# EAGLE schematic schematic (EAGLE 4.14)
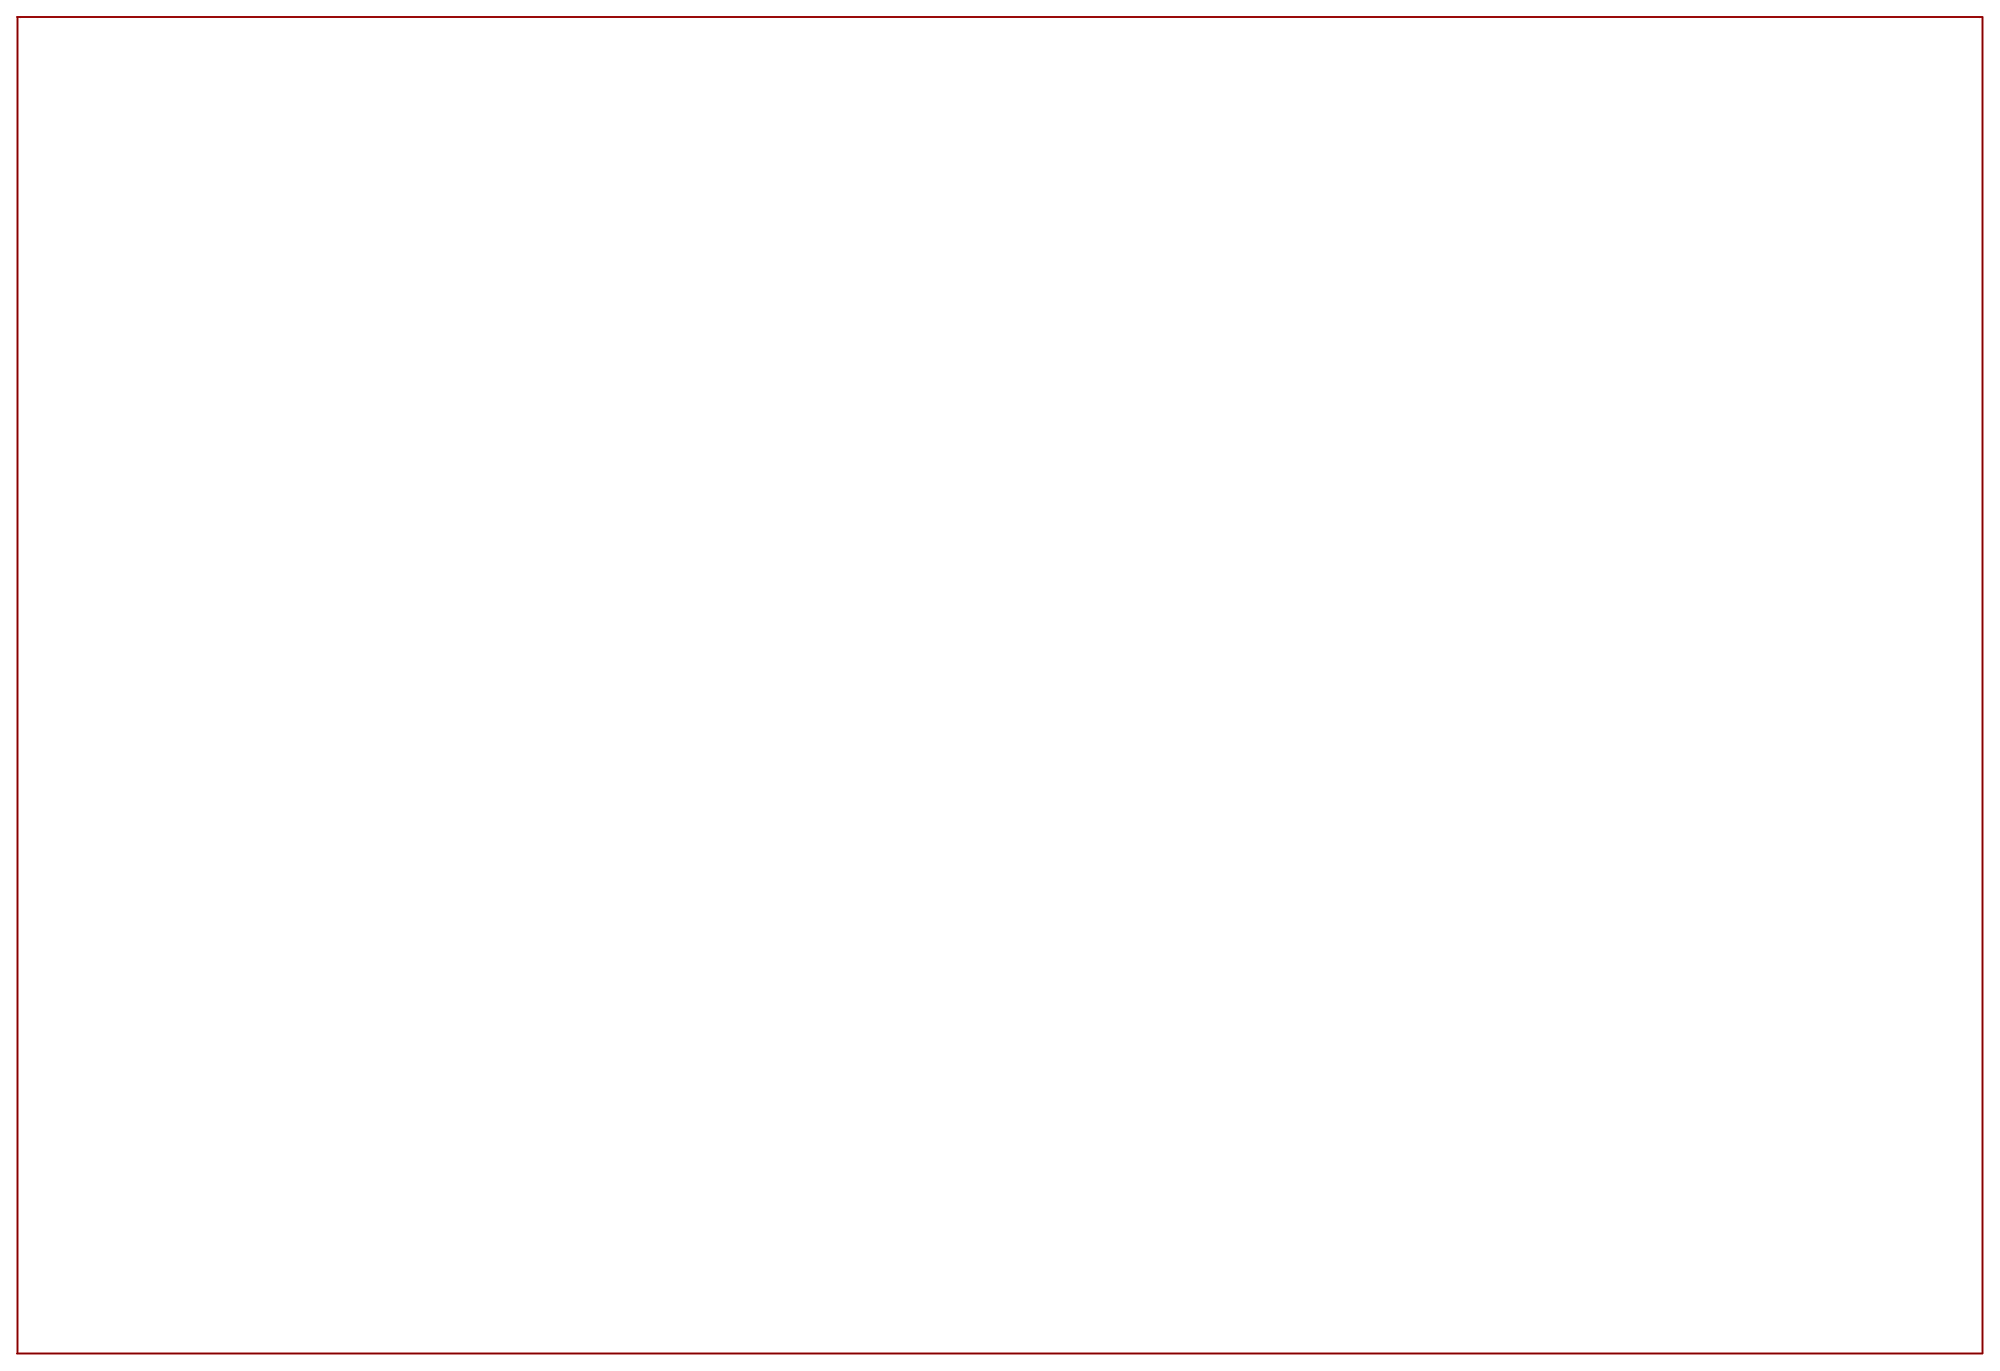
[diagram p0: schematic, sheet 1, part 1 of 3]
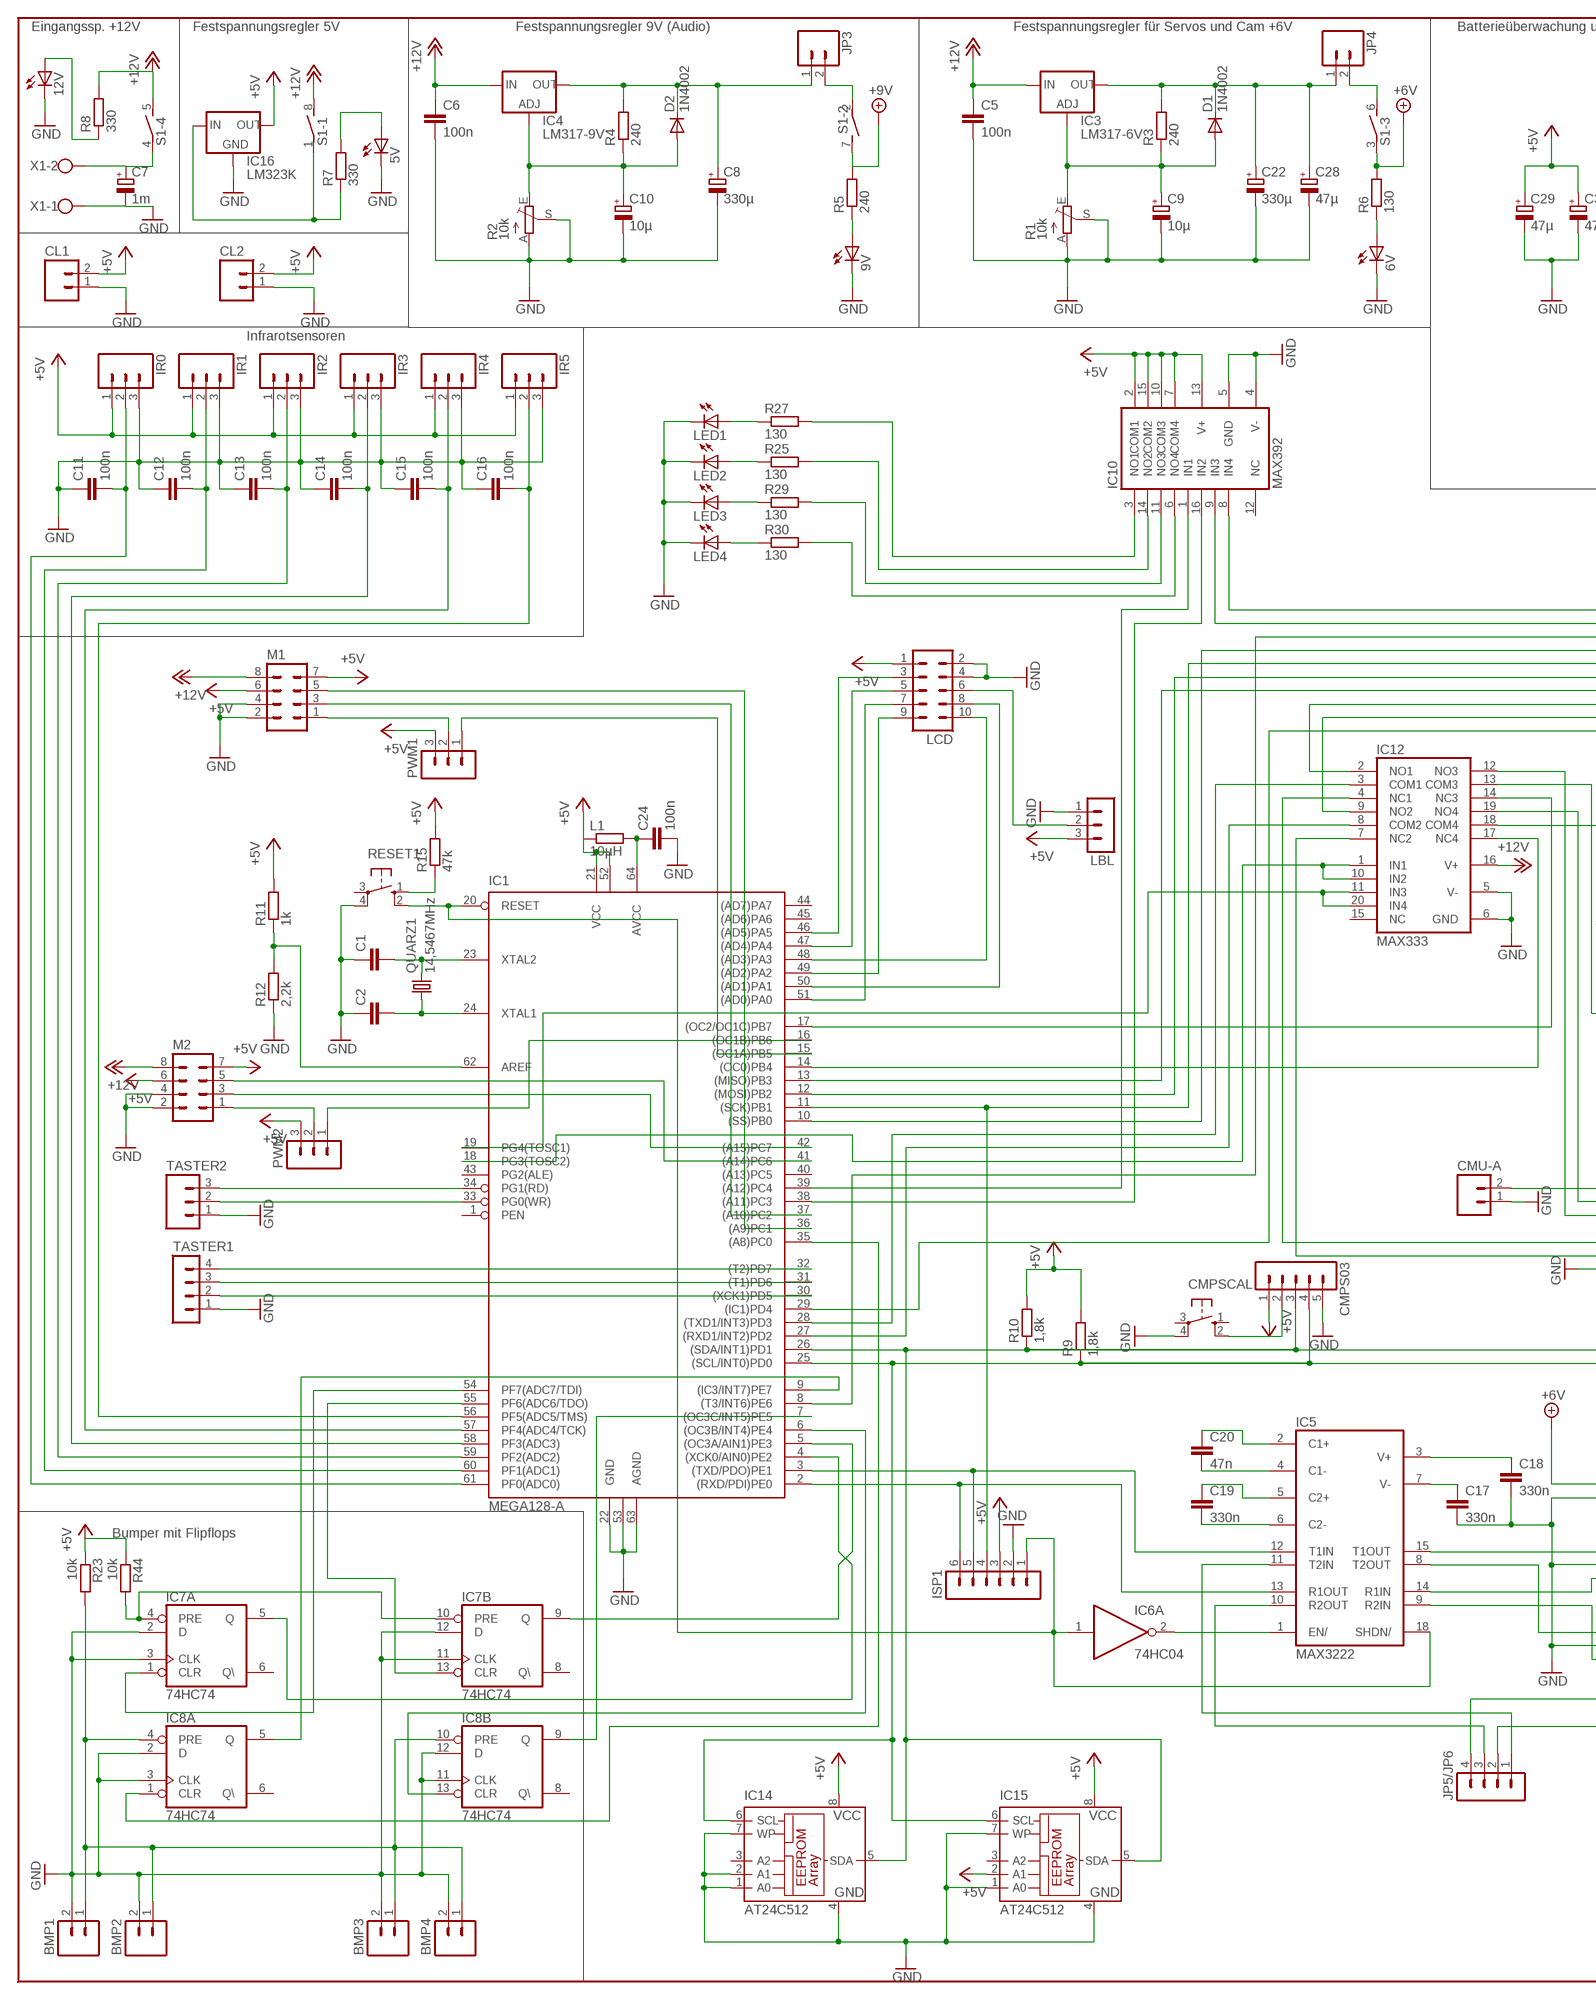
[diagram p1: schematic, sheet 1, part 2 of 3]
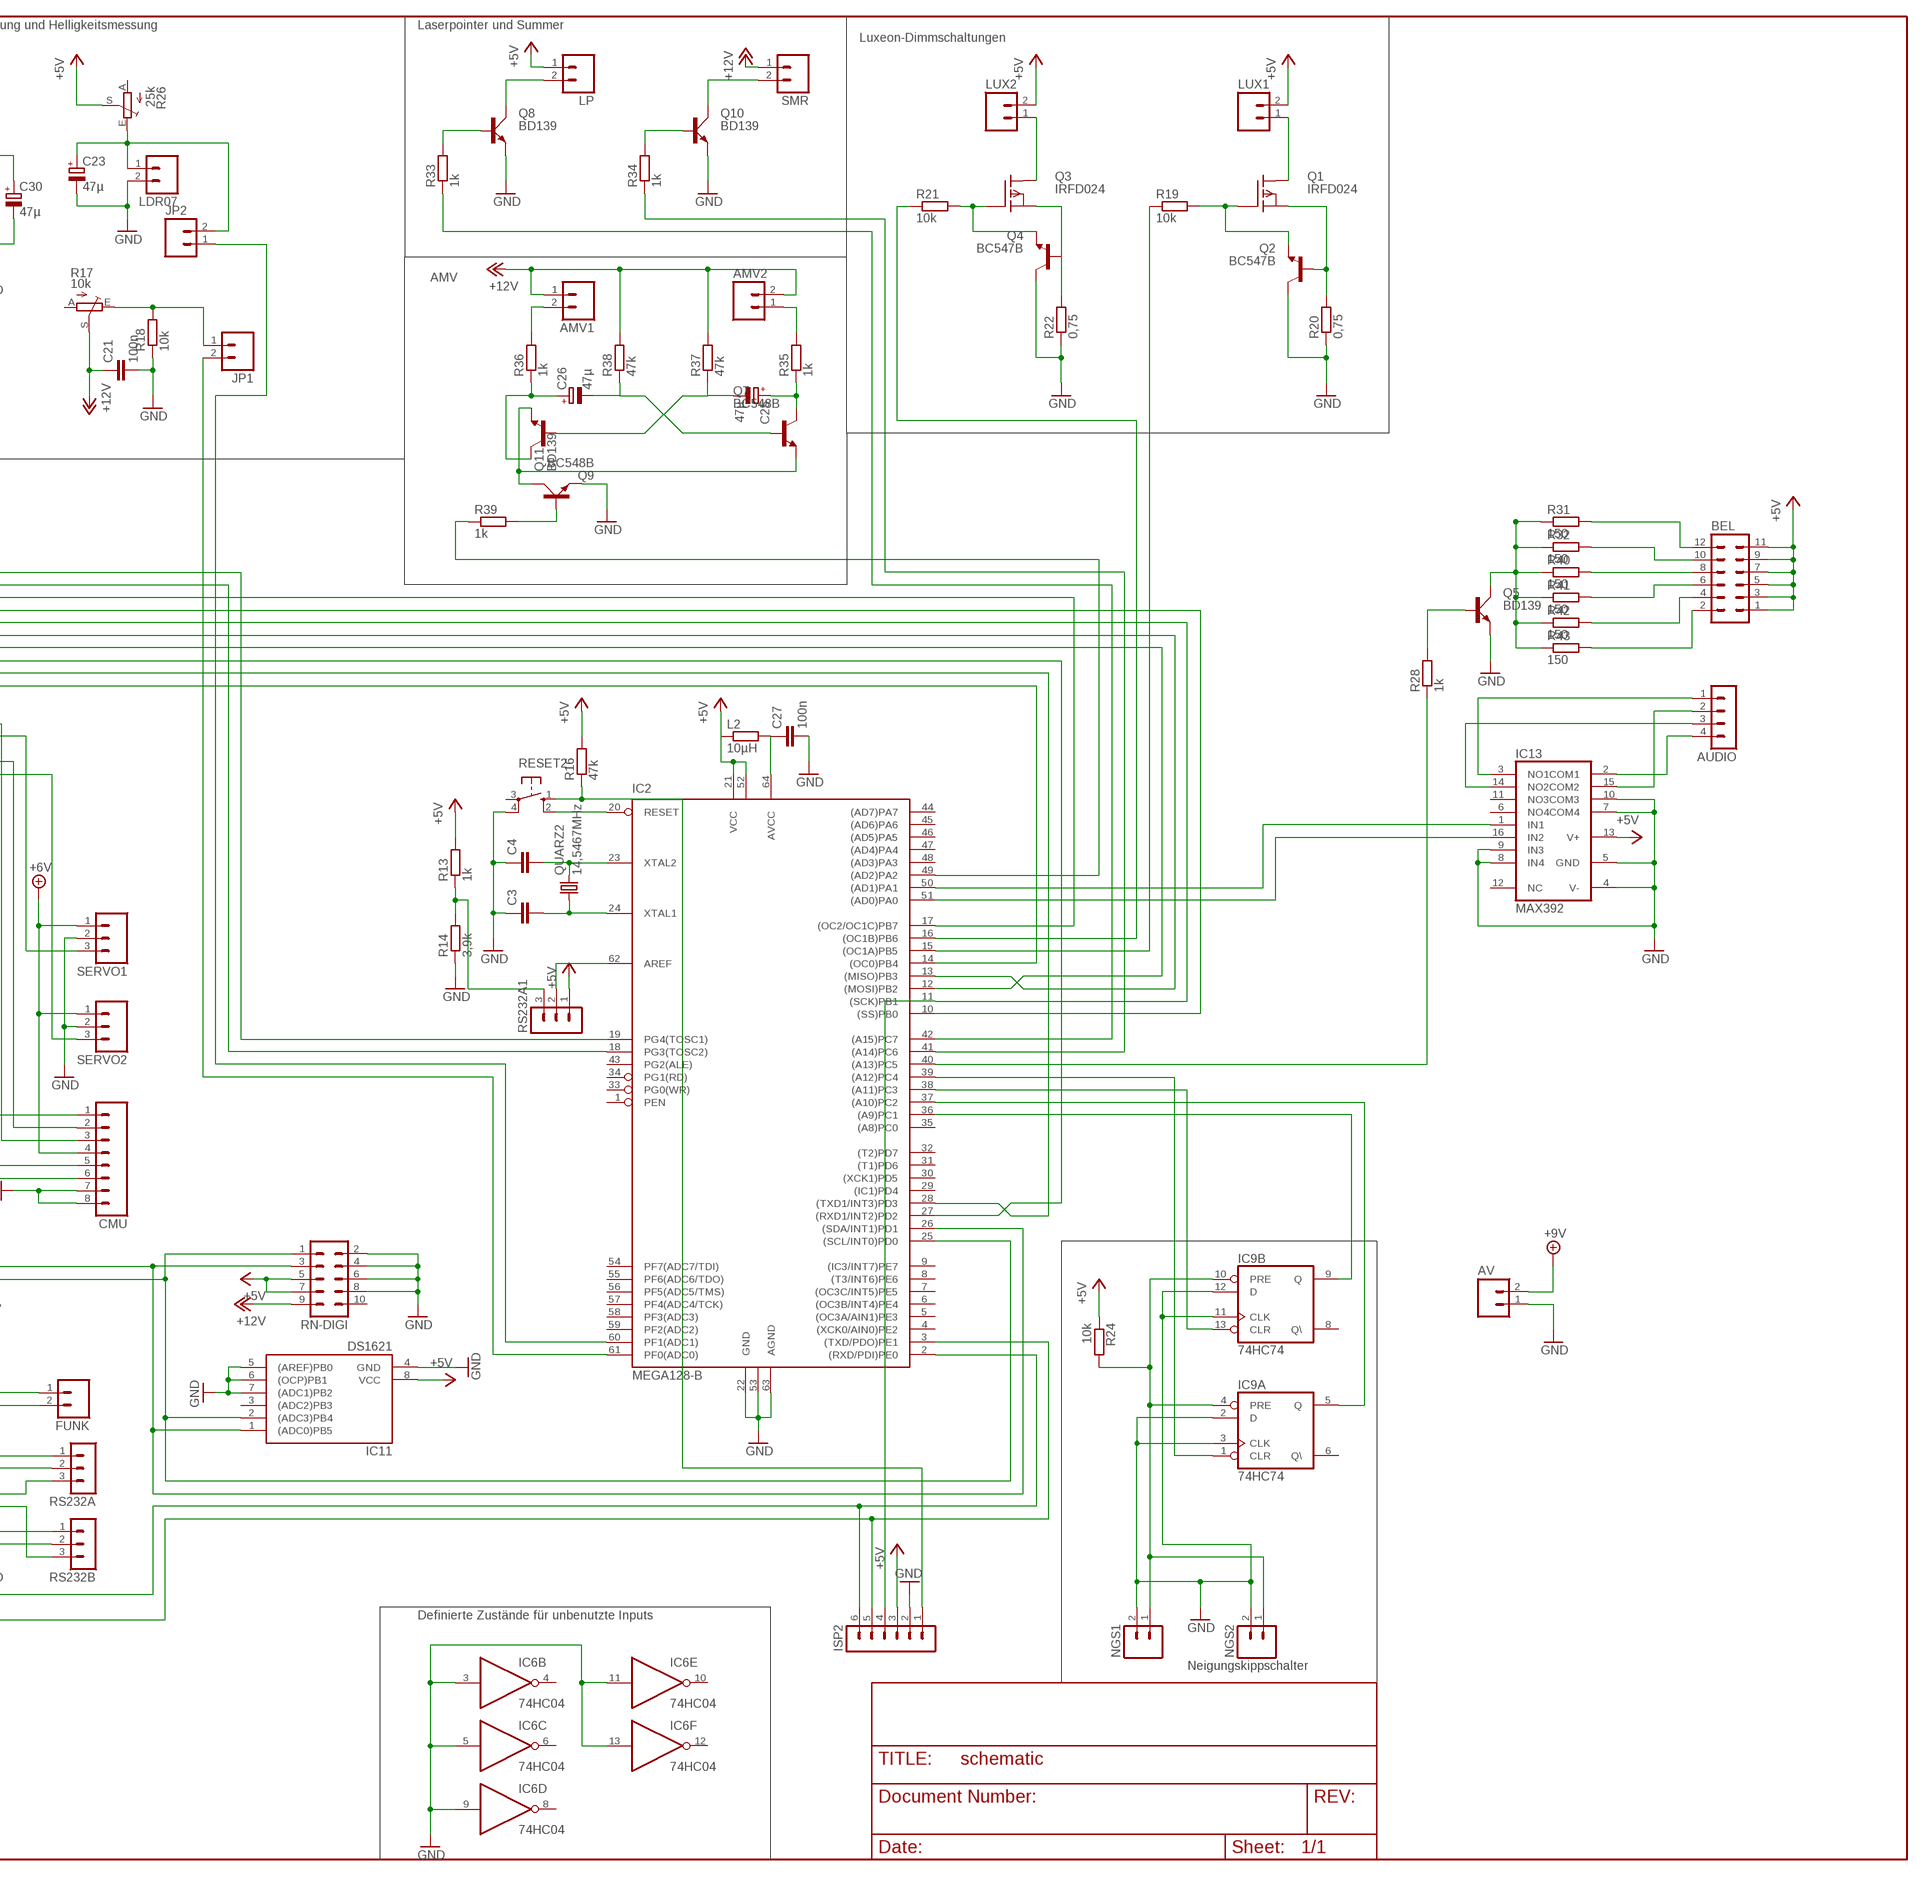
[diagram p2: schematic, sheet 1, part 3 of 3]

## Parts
5V  LEDCHIPLED_1206  [CHIPLED_1206]
6V  LEDCHIPLED_1206  [CHIPLED_1206]
9V  LEDCHIPLED_1206  [CHIPLED_1206]
12V  LEDCHIPLED_1206  [CHIPLED_1206]
AMV1  M02  [02P]
AMV2  M02  [02P]
AUDIO  MA04-1  [MA04-1]
AV  M02  [02P]
BEL  MA06-2  [MA06-2]
BMP1  M02  [02P]
BMP2  M02  [02P]
BMP3  M02  [02P]
BMP4  M02  [02P]
C1  C-EUC0805  [C0805]
C2  C-EUC0805  [C0805]
C3  C-EUC0805  [C0805]
C4  C-EUC0805  [C0805]
C5  100n  C-EUC1206  [C1206]
C6  100n  C-EUC1206  [C1206]
C7  1m  CPOL-EUE5-10.5  [E5-10,5]
C8  330µ  CPOL-EUE3.5-8  [E3,5-8]
C9  10µ  CPOL-EUE2-5  [E2-5]
C10  10µ  CPOL-EUE2-5  [E2-5]
C11  100n  C-EUC1206  [C1206]
C12  100n  C-EUC1206  [C1206]
C13  100n  C-EUC1206  [C1206]
C14  100n  C-EUC1206  [C1206]
C15  100n  C-EUC1206  [C1206]
C16  100n  C-EUC1206  [C1206]
C17  330n  C-EUC1812  [C1812]
C18  330n  C-EUC1812  [C1812]
C19  330n  C-EUC1812  [C1812]
C20  47n  C-EUC1206  [C1206]
C21  100n  C-EUC1206  [C1206]
C22  330µ  CPOL-EUE3.5-8  [E3,5-8]
C23  47µ  CPOL-EUE2-5  [E2-5]
C24  100n  C-EUC1206  [C1206]
C25  47µ  CPOL-EUE2-5  [E2-5]
C26  47µ  CPOL-EUE2-5  [E2-5]
C27  100n  C-EUC1206  [C1206]
C28  47µ  CPOL-EUE2-5  [E2-5]
C29  47µ  CPOL-EUE2-5  [E2-5]
C30  47µ  CPOL-EUE2-5  [E2-5]
CL1  M02  [02P]
CL2  M02  [02P]
CMPS03  MA05-1  [MA05-1]
CMPSCAL  10-XX  [B3F-10XX]
CMU  M08  [08P]
CMU-A  M02  [02P]
D1  1N4002  1N4004  [DO41-10]
D2  1N4002  1N4004  [DO41-10]
FUNK  M02  [02P]
IC1  MEGA128-A  [TQFP64-AEB]
IC2  MEGA128-B  MEGA128-A  [TQFP64-AEB]
IC3  LM317-6V  LM317TL  [317TL]
IC4  LM317-9V  LM317TL  [317TL]
IC5  MAX3222  MAX3222CPN  [DIL18]
IC6  74HC04  74HCT04D  [SO14]
IC7  74HC74  74HC74N  [DIL14]
IC8  74HC74  74HC74N  [DIL14]
IC9  74HC74  74HC74N  [DIL14]
IC10  MAX392  MAX392CSE  [SO16]
IC11  DS1621  TINY15LP  [DIL08]
IC12  MAX333  MAX333ACPP  [DIL20]
IC13  MAX392  MAX392CSE  [SO16]
IC14  AT24C512  24C01CP  [DIL8]
IC15  AT24C512  24C01CP  [DIL8]
IC16  LM323K  LM323-TO3  [TO3-K02]
IR0  M03  [03P]
IR1  M03  [03P]
IR2  M03  [03P]
IR3  M03  [03P]
IR4  M03  [03P]
IR5  M03  [03P]
ISP1  MA06-1  [MA06-1]
ISP2  MA06-1  [MA06-1]
JP1  M02  [02P]
JP2  M02  [02P]
JP3  M02  [02P]
JP4  M02  [02P]
JP5/JP6  MA04-1  [MA04-1]
L1  10µH  R-EU_R1206  [R1206]
L2  10µH  R-EU_R1206  [R1206]
LBL  MA03-1  [MA03-1]
LCD  ML10  [ML10]
LDR07  M02  [02P]
LED1  LEDCHIPLED_1206  [CHIPLED_1206]
LED2  LEDCHIPLED_1206  [CHIPLED_1206]
LED3  LEDCHIPLED_1206  [CHIPLED_1206]
LED4  LEDCHIPLED_1206  [CHIPLED_1206]
LP  M02  [02P]
LUX1  M02  [02P]
LUX2  M02  [02P]
M1  MA04-2  [MA04-2]
M2  MA04-2  [MA04-2]
NGS1  M02  [02P]
NGS2  M02  [02P]
PWM1  MA03-1  [MA03-1]
PWM2  MA03-1  [MA03-1]
Q1  IRFD024  IRFD9210  [DIL04]
Q2  BC547B  [TO92]
Q3  IRFD024  IRFD9210  [DIL04]
Q4  BC547B  [TO92]
Q5  BD139  [TO126AV]
Q7  BC548B  [TO92-EBC]
Q8  BD139  [TO126AV]
Q9  BC548B  [TO92-EBC]
Q10  BD139  [TO126AV]
Q11  BD139  [TO126AV]
QUARZ1  14,5467MHz  CRYTALHC49UP  [HC49UP]
QUARZ2  14,5467MHz  CRYTALHC49UP  [HC49UP]
R1  10k  TRIM_EU-ST10  [ST10]
R2  10k  TRIM_EU-ST10  [ST10]
R3  240  R-EU_R1206  [R1206]
R4  240  R-EU_R1206  [R1206]
R5  240  R-EU_R0805  [R0805]
R6  130  R-EU_R0805  [R0805]
R7  330  R-EU_R0805  [R0805]
R8  330  R-EU_R0805  [R0805]
R9  1,8k  R-EU_R0805  [R0805]
R10  1,8k  R-EU_R0805  [R0805]
R11  1k  R-EU_R0805  [R0805]
R12  2,2k  R-EU_R0805  [R0805]
R13  1k  R-EU_R0805  [R0805]
R14  3,9k  R-EU_R0805  [R0805]
R15  47k  R-EU_R0805  [R0805]
R16  47k  R-EU_R0805  [R0805]
R17  10k  TRIM_EU-S43P  [SP19L]
R18  10k  R-EU_R0805  [R0805]
R19  10k  R-EU_R0805  [R0805]
R20  0,75  R-EU_0411/15  [0411/15]
R21  10k  R-EU_R0805  [R0805]
R22  0,75  R-EU_0411/15  [0411/15]
R23  10k  R-EU_R0805  [R0805]
R24  10k  R-EU_R0805  [R0805]
R25  130  R-EU_R0805  [R0805]
R26  25k  TRIM_EU-ST10  [ST10]
R27  130  R-EU_R0805  [R0805]
R28  1k  R-EU_R0805  [R0805]
R29  130  R-EU_R0805  [R0805]
R30  130  R-EU_R0805  [R0805]
R31  150  R-EU_R0805  [R0805]
R32  150  R-EU_R0805  [R0805]
R33  1k  R-EU_R0805  [R0805]
R34  1k  R-EU_R0805  [R0805]
R35  1k  R-EU_R0805  [R0805]
R36  1k  R-EU_R0805  [R0805]
R37  47k  R-EU_R0805  [R0805]
R38  47k  R-EU_R0805  [R0805]
R39  1k  R-EU_R0805  [R0805]
R40  150  R-EU_R0805  [R0805]
R41  150  R-EU_R0805  [R0805]
R42  150  R-EU_R0805  [R0805]
R43  150  R-EU_R0805  [R0805]
R44  10k  R-EU_R0805  [R0805]
RESET1  10-XX  [B3F-10XX]
RESET2  10-XX  [B3F-10XX]
RN-DIGI  ML10  [ML10]
RS232A  MA03-1  [MA03-1]
RS232A1  MA03-1  [MA03-1]
RS232B  MA03-1  [MA03-1]
S1  DIP04S  [DIP04S]
SERVO1  M03  [03P]
SERVO2  M03  [03P]
SMR  M02  [02P]
TASTER1  MA04-1  [MA04-1]
TASTER2  M03  [03P]
X1  W237-02P  [W237-132]

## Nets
+5V: BEL.1 BEL.3 BEL.5 BEL.7 BEL.9 BEL.11 C29.+ C30.+ CL1.2 CL2.2 CMPS03.1 IC1.21(VCC) IC1.52(VCC1) IC2.21(VCC) IC2.52(VCC1) IC10.2(COM1) IC10.7(COM4) IC10.10(COM3) IC10.13(V+) IC10.15(COM2) IC11.8(VCC) IC13.13(V+) IC14.8(VCC) IC15.2(A1) IC15.8(VCC) IC16.1(OUT) IR0.1 IR1.1 IR2.1 IR3.1 IR4.1 IR5.1 ISP1.3 ISP2.3 L1.1 L2.1 LBL.3 LCD.1 LP.1 LUX1.2 LUX2.2 M1.6 M1.7 M2.6 M2.7 PWM1.3 PWM2.3 R9.2 R10.2 R11.2 R13.2 R15.2 R16.2 R23.1 R24.1 R26.S R44.1 RN-DIGI.5 RN-DIGI.7 RS232A1.1
+7V: CMU.4 FUNK.1 R6.2 S1.3 SERVO1.1 SERVO2.1 ; supply symbol labelled +6V
+9V: AV.2 R5.2 S1.7
+12V: AMV1.1 AMV2.2 C5.1 C6.1 C21.1 IC3.3(IN) IC4.3(IN) IC12.16(V+) M1.8 M2.8 R8.2 R17.S R37.2 R38.2 RN-DIGI.9 S1.5 S1.8 SMR.1
GND: 5V.C 6V.C 9V.C 12V.C AV.1 BMP1.2 BMP2.2 BMP3.2 BMP4.2 C1.1 C2.1 C3.1 C4.1 C5.2 C6.2 C7.- C8.- C9.- C10.- C11.1 C12.1 C13.1 C14.1 C15.1 C16.1 C17.2 C18.2 C21.2 C22.- C23.- C24.2 C27.2 C28.- C29.- C30.- CL1.1 CL2.1 CMPS03.5 CMPSCAL.4(P1) CMU-A.1 CMU.7 CMU.8 FUNK.2 IC1.22(GND) IC1.53(GND1) IC1.63(AGND) IC2.22(GND) IC2.53(GND1) IC2.63(AGND) IC6.3(B:I) IC6.5(C:I) IC6.9(D:I) IC6.11(E:I) IC6.13(F:I) IC7.2(A:D) IC7.3(A:CLK) IC7.11(B:CLK) IC7.12(B:D) IC8.2(A:D) IC8.3(A:CLK) IC8.11(B:CLK) IC8.12(B:D) IC9.2(A:D) IC9.3(A:CLK) IC9.11(B:CLK) IC9.12(B:D) IC10.4(V-) IC10.5(GND) IC11.4(GND) IC11.5((AREF)PB0) IC11.6((OCP)PB1) IC11.7((ADC1)PB2) IC12.5(V-) IC12.6(GND) IC13.4(V-) IC13.5(GND) IC13.7(COM4) IC13.8(IN4) IC13.9(IN3) IC13.10(COM3) IC14.1(A0) IC14.2(A1) IC14.4(GND) IC14.7(WP) IC15.1(A0) IC15.4(GND) IC15.7(WP) IC16.3(GND) IR0.3 IR1.3 IR2.3 IR3.3 IR4.3 IR5.3 ISP1.2 ISP2.2 LBL.1 LCD.2 LCD.4 LDR07.2 LED1.C LED2.C LED3.C LED4.C M1.2 M1.4 M2.2 M2.4 NGS1.2 NGS2.2 Q2.3(C) Q4.3(C) Q5.E Q8.E Q10.E Q11.E R1.A R1.S R2.A R2.S R12.1 R14.1 R18.1 R20.1 R22.1 RESET1.4(P1) RESET2.4(P1) RN-DIGI.2 RN-DIGI.4 RN-DIGI.6 RN-DIGI.8 RS232A.2 RS232B.2 SERVO1.2 SERVO2.2 TASTER1.1 TASTER2.1 X1.1
N$1: C2.2 IC1.24(XTAL1) QUARZ1.1
N$2: C1.2 IC1.23(XTAL2) QUARZ1.2
N$3: C3.2 IC2.24(XTAL1) QUARZ2.1
N$4: C4.2 IC2.23(XTAL2) QUARZ2.2
N$5: C8.+ D2.C IC4.2(OUT) JP3.1 R4.2
N$6: C22.+ C28.+ D1.C IC3.2(OUT) JP4.1 R3.2
N$7: C7.+ S1.4 X1.2
N$8: 5V.A R7.2
N$9: 6V.A R6.1
N$10: IC16.2(IN) R7.1 S1.1
N$11: 9V.A R5.1
N$12: 12V.A R8.1
N$13: C9.+ D1.A IC3.1(ADJ) R1.E R3.1
N$14: CMPS03.3 IC1.26((SDA/INT1)PD1) IC2.26((SDA/INT1)PD1) IC11.1((ADC0)PB5) IC14.5(SDA) IC15.5(SDA) R10.1 RN-DIGI.3
N$16: IC2.20(RESET) RESET2.2(S1)
N$17: C10.+ D2.A IC4.1(ADJ) R2.E R4.1
N$18: IC1.20(RESET) IC5.18(SHDN/) IC6.1(A:I) ISP1.1 RESET1.2(S1)
N$19: CMU.3 IC12.12(NO3)
N$20: IC1.62(AREF) R11.1 R12.2
N$21: JP3.2 S1.2
N$22: CMU.6 IC12.7(NC2)
N$23: R13.1 R14.2 RS232A1.3
N$24: CMU.5 IC12.4(NC1)
N$25: IC1.14((OC0)PB4) IC12.17(NC4)
N$26: IC1.17((OC2/OC1C)PB7) IC12.14(NC3)
N$27: IC1.29((IC1)PD4) IC2.14((OC0)PB4)
N$28: CMU.2 IC12.19(NO4)
N$29: IC12.13(COM3) SERVO1.3
N$30: IC12.18(COM4) SERVO2.3
N$31: IC1.2((RXD/PDI)PE0) IC5.13(R1OUT) ISP1.6
N$32: CMU-A.2 CMU.1
N$33: IC1.3((TXD/PDO)PE1) IC5.12(T1IN) ISP1.5
N$34: CMPS03.2 CMPSCAL.2(S1)
N$35: IC2.62(AREF) RS232A1.2
N$36: CMPS03.4 IC1.25((SCL/INT0)PD0) IC2.25((SCL/INT0)PD0) IC11.2((ADC3)PB4) IC14.6(SCL) IC15.6(SCL) R9.1 RN-DIGI.1
N$38: IC5.14(R1IN) RS232A.3
N$39: IC5.15(T1OUT) RS232A.1
N$40: C17.1 IC5.7(V-)
N$44: IC2.2((RXD/PDI)PE0) ISP2.6 JP5/JP6.4
N$45: C11.2 IC1.61(PF0(ADC0)) IR0.2
N$46: C12.2 IC1.60(PF1(ADC1)) IR1.2
N$47: C13.2 IC1.59(PF2(ADC2)) IR2.2
N$48: C14.2 IC1.58(PF3(ADC3)) IR3.2
N$49: C15.2 IC1.57(PF4(ADC4/TCK)) IR4.2
N$50: C16.2 IC1.56(PF5(ADC5/TMS)) IR5.2
N$51: IC2.3((TXD/PDO)PE1) ISP2.5 JP5/JP6.2
N$52: IC5.8(T2OUT) RS232B.1
N$53: IC5.9(R2IN) RS232B.3
N$54: C18.1 IC5.3(V+)
N$55: R15.1 RESET1.1(S)
N$56: C19.2 IC5.6(C2-)
N$57: C19.1 IC5.5(C2+)
N$58: C20.2 IC5.4(C1-)
N$59: C20.1 IC5.2(C1+)
N$60: ISP2.1 R16.1 RESET2.1(S)
N$61: IC5.10(R2OUT) JP5/JP6.3
N$62: IC5.11(T2IN) JP5/JP6.1
N$63: JP1.1 R17.E R18.2
N$64: IC1.10((SS)PB0) IC2.10((SS)PB0)
N$65: IC1.11((SCK)PB1) IC2.11((SCK)PB1) ISP1.4 ISP2.4
N$66: IC5.1(EN/) IC6.2(A:O)
N$67: IC1.12((MOSI)PB2) IC2.13((MISO)PB3)
N$68: IC1.13((MISO)PB3) IC2.12((MOSI)PB2)
N$69: Q1.2(S) Q2.2(B) R20.2
N$70: Q1.1(G) Q2.1(E) R19.2
N$71: LUX1.1 Q1.3(D1)
N$72: IC2.15((OC1A)PB5) R19.1
N$73: IC2.18(PG3(TOSC2)) IC10.9(IN3)
N$74: Q3.2(S) Q4.2(B) R22.2
N$75: Q3.1(G) Q4.1(E) R21.2
N$76: LUX2.1 Q3.3(D1)
N$78: IC2.16((OC1B)PB6) R21.1
N$79: JP4.2 S1.6
N$80: IC10.6(NO4) R30.2
N$81: IC1.28((TXD1/INT3)PD3) IC12.3(COM1)
N$82: IC1.8((T3/INT6)PE6) IC2.17((OC2/OC1C)PB7)
N$83: IC1.27((RXD1/INT2)PD2) IC12.8(COM2)
N$84: IC2.28((TXD1/INT3)PD3) IC12.9(NO2)
N$86: IC2.27((RXD1/INT2)PD2) IC12.2(NO1)
N$87: BMP1.1 BMP2.1 BMP3.1 BMP4.1 IC8.4(A:PRE) IC8.10(B:PRE) R23.2
N$88: IC1.54(PF7(ADC7/TDI)) IC7.1(A:CLR)
N$89: IC1.55(PF6(ADC6/TDO)) IC7.13(B:CLR)
N$91: IC1.5((OC3A/AIN1)PE3) IC7.9(B:Q)
N$92: IC1.9((IC3/INT7)PE7) IC8.5(A:Q)
N$93: IC1.7((OC3C/INT5)PE5) IC8.9(B:Q)
N$96: IC10.11(NO3) R29.2
N$97: IC1.4((XCK0/AIN0)PE2) IC7.5(A:Q)
N$98: IC1.6((OC3B/INT4)PE4) IC8.13(B:CLR)
N$99: C24.1 IC1.64(AVCC) L1.2
N$101: IC1.30((XCK1)PD5) TASTER1.2
N$102: IC9.4(A:PRE) IC9.10(B:PRE) NGS1.1 NGS2.1 R24.2
N$103: IC1.46((AD5)PA5) LCD.3
N$105: IC2.36((A9)PC1) IC9.9(B:Q)
N$106: IC2.38((A11)PC3) IC9.13(B:CLR)
N$107: IC2.39((A12)PC4) IC9.1(A:CLR)
N$108: IC2.37((A10)PC2) IC9.5(A:Q)
N$109: IC1.47((AD4)PA4) LCD.5
N$110: IC1.48((AD3)PA3) LCD.10
N$111: IC1.49((AD2)PA2) LCD.9
N$112: IC1.50((AD1)PA1) LCD.8
N$113: IC1.51((AD0)PA0) LCD.7
N$114: IC1.31((T1)PD6) TASTER1.3
N$115: IC1.32((T2)PD7) TASTER1.4
N$116: IC2.61(PF0(ADC0)) JP1.2
N$117: C23.+ JP2.2 LDR07.1 R26.E
N$118: IC10.14(NO2) R25.2
N$119: IC2.60(PF1(ADC1)) JP2.1
N$120: IC10.3(NO1) R27.2
N$121: BEL.2 R43.2
N$122: Q5.B R28.2
N$123: LED1.A R27.1
N$124: IC1.18(PG3(TOSC2)) IC12.1(IN1) IC12.10(IN2)
N$125: IC1.19(PG4(TOSC1)) IC12.11(IN3) IC12.20(IN4)
N$126: LED2.A R25.1
N$127: Q8.B R33.2
N$128: LED3.A R29.1
N$129: IC1.34(PG1(RD)) TASTER2.3
N$130: IC1.33(PG0(WR)) TASTER2.2
N$131: IC2.41((A14)PC6) R34.1
N$132: LED4.A R30.1
N$133: Q10.B R34.2
N$134: IC2.42((A15)PC7) R33.1
N$135: LP.2 Q8.C
N$136: Q10.C SMR.2
N$137: C25.+ Q7.C R35.1
N$138: C26.+ Q9.C R36.1
N$139: Q11.B R39.2
N$140: IC2.49((AD2)PA2) R39.1
N$141: AMV1.2 R36.2
N$142: C26.- Q7.B R38.1
N$143: C25.- Q9.B R37.1
N$144: Q7.E Q9.E Q11.C
N$145: AMV2.1 R35.2
N$146: BEL.10 R32.2
N$147: BEL.12 R31.2
N$148: IC1.39((A12)PC4) IC10.1(IN1)
N$149: IC1.38((A11)PC3) IC10.16(IN2)
N$150: IC2.19(PG4(TOSC1)) IC10.8(IN4)
N$151: BEL.8 R40.2
N$152: BEL.6 R41.2
N$153: BEL.4 R42.2
N$154: IC2.40((A13)PC5) R28.1
N$155: Q5.C R31.1 R32.1 R40.1 R41.1 R42.1 R43.1
N$156: AUDIO.2 IC13.15(COM2)
N$157: AUDIO.4 IC13.2(COM1)
N$158: IC2.50((AD1)PA1) IC13.1(IN1)
N$159: IC2.51((AD0)PA0) IC13.16(IN2)
N$160: AUDIO.1 IC13.3(NO1)
N$161: AUDIO.3 IC13.14(NO2)
N$162: IC1.15((OC1A)PB5) PWM1.1
N$163: M2.1 PWM2.2
N$164: IC1.37((A10)PC2) M1.3
N$165: IC1.36((A9)PC1) M1.5
N$166: IC1.16((OC1B)PB6) PWM2.1
N$167: IC1.42((A15)PC7) M2.3
N$168: IC1.41((A14)PC6) M2.5
N$169: M1.1 PWM1.2
N$170: IC1.35((A8)PC0) IC8.1(A:CLR)
N$171: C27.1 IC2.64(AVCC) L2.2
N$394: IC7.4(A:PRE) IC7.10(B:PRE) R44.2
N$576: LBL.2 LCD.6
Unconnected: CMPSCAL.1(S) CMPSCAL.3(P) IC1.1(PEN) IC1.40((A13)PC5) IC1.43(PG2(ALE)) IC1.44((AD7)PA7) IC1.45((AD6)PA6) IC2.1(PEN) IC2.4((XCK0/AIN0)PE2) IC2.5((OC3A/AIN1)PE3) IC2.6((OC3B/INT4)PE4) IC2.7((OC3C/INT5)PE5) IC2.8((T3/INT6)PE6) IC2.9((IC3/INT7)PE7) IC2.29((IC1)PD4) IC2.30((XCK1)PD5) IC2.31((T1)PD6) IC2.32((T2)PD7) IC2.33(PG0(WR)) IC2.34(PG1(RD)) IC2.35((A8)PC0) IC2.43(PG2(ALE)) IC2.44((AD7)PA7) IC2.45((AD6)PA6) IC2.46((AD5)PA5) IC2.47((AD4)PA4) IC2.48((AD3)PA3) IC2.54(PF7(ADC7/TDI)) IC2.55(PF6(ADC6/TDO)) IC2.56(PF5(ADC5/TMS)) IC2.57(PF4(ADC4/TCK)) IC2.58(PF3(ADC3)) IC2.59(PF2(ADC2)) IC6.4(B:O) IC6.6(C:O) IC6.8(D:O) IC6.10(E:O) IC6.12(F:O) IC7.6(A:Q\) IC7.8(B:Q\) IC8.6(A:Q\) IC8.8(B:Q\) IC9.6(A:Q\) IC9.8(B:Q\) IC10.12(NC) IC11.3((ADC2)PB3) IC12.15(NC) IC13.6(NO4) IC13.11(NO3) IC13.12(NC) IC14.3(A2) IC15.3(A2) Q1.4(D) Q3.4(D) R17.A R26.A RESET1.3(P) RESET2.3(P) RN-DIGI.10

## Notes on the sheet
- Eingangssp. +12V | Festspannungsregler 5V | Festspannungsregler 9V (Audio) | Festspannungsregler für Servos und Cam +6V | Batterieüberwachung und Helligkeitsmessung | Laserpointer und Summer
- Luxeon-Dimmschaltungen
- AMV
- Infrarotsensoren
- Bumper mit Flipflops
- Definierte Zustände für unbenutzte Inputs
- Neigungskippschalter

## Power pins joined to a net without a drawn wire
GND: IC5.16(GND) IC6.7(P:GND) IC7.7(P:GND) IC8.7(P:GND) IC9.7(P:GND)
VCC: IC5.17(VCC) IC6.14(P:VCC) IC7.14(P:VCC) IC8.14(P:VCC) IC9.14(P:VCC)

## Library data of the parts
5V 6V 9V 12V LED1-LED4 = led:LED: LED
AMV1 AMV2 AV BMP1-BMP4 CL1 CL2 CMU-A FUNK JP1-JP4 LDR07 LP LUX1 LUX2 NGS1 NGS2 SMR = con-amp-quick:M02: AMP QUICK CONNECTOR
AUDIO JP5/JP6 TASTER1 = con-lstb:MA04-1: PIN HEADER
BEL = con-lstb:MA06-2: PIN HEADER
C1-C6 C11-C21 C24 C27 = rcl:C-EU: CAPACITOR, European symbol
C7-C10 C22 C23 C25 C26 C28-C30 = rcl:CPOL-EU: POLARIZED CAPACITOR, European symbol
CMPS03 = con-lstb:MA05-1: PIN HEADER
CMPSCAL RESET1 RESET2 = switch-omron:10-XX: OMRON SWITCH
CMU = con-amp-quick:M08: AMP QUICK CONNECTOR
D1 D2 = diode:1N4004: DIODE
IC1 IC2 = atmel:MEGA128: MICROCONTROLLER 128 Kbytes FLASH 4 Kbytes SRAM 4 Kbytes EEPROM DUAL USART 8-channel 10 bit ADC
IC3 IC4 = v-reg:LM317TL: VOLTAGE REGULATOR
IC5 = TBKMaxim:MAX3222: RS232 TRANSEIVER
IC6 = 74xx-eu:74*04: Hex INVERTER
IC7-IC9 = 74xx-eu:74*74: Dual D type positive edge triggered FLIP FLOP, preset and clear
IC10 IC13 = maxim:MAX392CSE: ANALOG SWITCH
IC11 = atmel-flash:TINY15L: MICROCONTROLLER 2.7 V 1 Kbytes FLASH 64 bytes EEPROM 4-channel 10 bit ADC
IC12 = maxim:MAX333ACPP: ANALOG SWITCH
IC14 IC15 = microchip:24C*: Serial EEPROM 1 K/2 K/4 K
IC16 = v-reg:LM323-TO3: VOLTAGE REGULATOR
IR0 IR1-IR5 SERVO1 SERVO2 TASTER2 = con-amp-quick:M03: AMP QUICK CONNECTOR
ISP1 ISP2 = con-lstb:MA06-1: PIN HEADER
L1 L2 R3-R16 R18-R25 R27-R44 = rcl:R-EU_: RESISTOR, European symbol
LBL PWM1 PWM2 RS232A RS232A1 RS232B = con-lstb:MA03-1: PIN HEADER
LCD RN-DIGI = con-harting-ml:ML10: HARTING
M1 M2 = con-lstb:MA04-2: PIN HEADER
Q1 Q3 = transistor-fet:IRFD9210: P-Channel Enhancement MOSFET
Q2 Q4 = transistor-npn:BC547*: NPN Transistor
Q5 Q8 Q10 Q11 = transistor-power:BD139: NPN TRANSISTOR
Q7 Q9 = transistor-npn:BC548*: NPN Transistor
QUARZ1 QUARZ2 = crystal:CRYTAL: CRYSTAL
R1 R2 R17 R26 = pot:TRIM_EU-: POTENTIOMETER
S1 = switch-dil:DIP04S: DIL/CODE SWITCH
X1 = con-wago-508:W237-02P: WAGO SREW CLAMP

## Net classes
1 Power4A: width 1.143 mm
2 Power2A: width 0.762 mm
3 Power3A: width 1.016 mm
